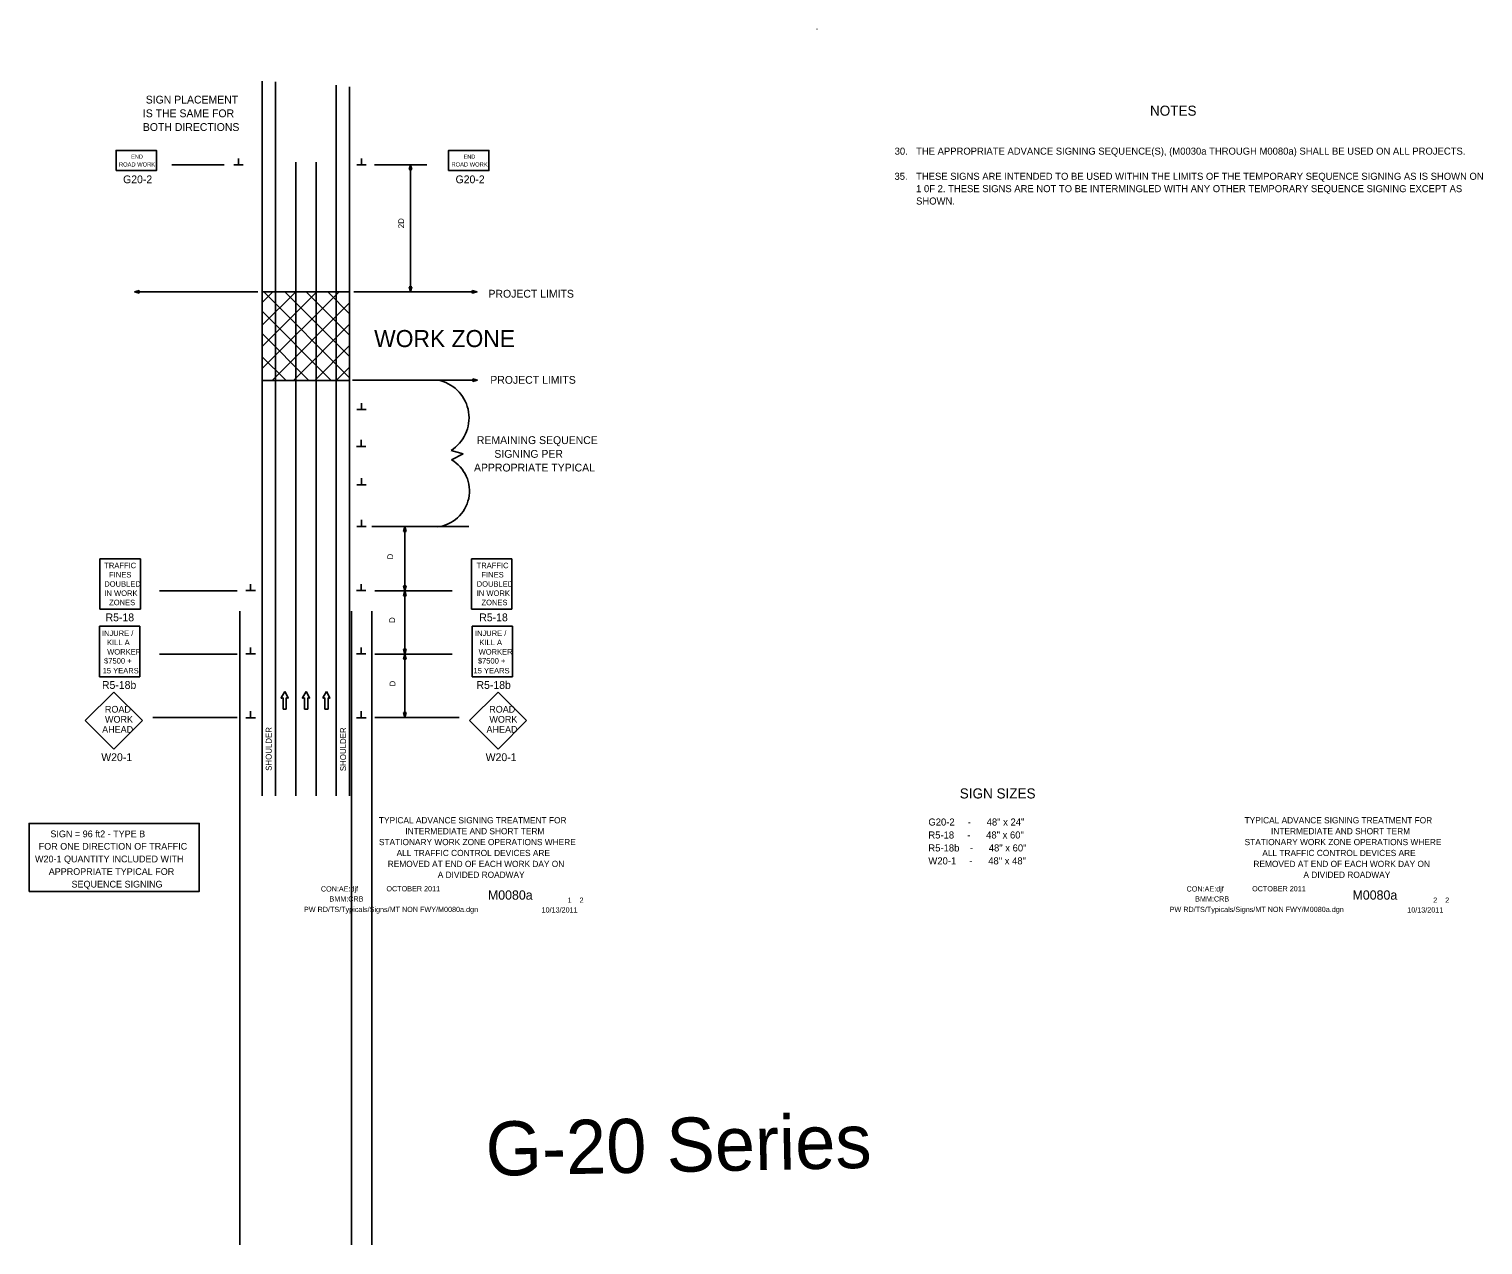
# Model space of a CAD drawing. Extents: x 16733 to 18461, y 5466 to 6911.
import ezdxf

# ---------------------------------------------------------------- set-up
doc = ezdxf.new("R2010")
doc.units = 0
for name, color, linetype in [('BORDER', 7, 'Continuous'), ('BORDER_SIGNAL_WO', 7, 'Continuous'), ('MT_SCRATCH_LEVEL_E', 7, 'Continuous'), ('PAVT_EDGE_EX', 7, 'Continuous'), ('TRAFFIC_SIGNS_PR', 7, 'Continuous'), ('TYPICAL_TEXT_DIMEN_PR', 7, 'Continuous')]:
    doc.layers.add(name, color=color, linetype=linetype)

msp = doc.modelspace()

# ---------------------------------------------------------------- linework, layer by layer
at = {"layer": 'BORDER'}
for p, q in [((17278.5, 5932.8), (17278.5, 5932.8)), ((18307.5, 5932.8), (18307.5, 5932.8)), ((18307.5, 5932.8), (18307.5, 5932.8))]:
    msp.add_line(p, q, dxfattribs=at)
at = {"layer": 'BORDER_SIGNAL_WO'}
msp.add_line((17670, 6911.2), (17669.5, 6911.3), dxfattribs=at)
at = {"layer": 'MT_SCRATCH_LEVEL_E'}
for p, q in [((17036.9, 6123.6), (17032.8, 6116.3)), ((17036.9, 6123.6), (17032.8, 6116.3)), ((17041, 6116.3), (17036.9, 6123.6)), ((17041, 6116.3), (17036.9, 6123.6)), ((17062.3, 6123.6), (17058.2, 6116.3)), ((17062.3, 6123.6), (17058.2, 6116.3)), ((17066.5, 6116.3), (17062.3, 6123.6)), ((17066.5, 6116.3), (17062.3, 6123.6)), ((17086.5, 6123.6), (17082.4, 6116.3)), ((17086.5, 6123.6), (17082.4, 6116.3)), ((17090.7, 6116.3), (17086.5, 6123.6)), ((17090.7, 6116.3), (17086.5, 6123.6)), ((17033.3, 6115.6), (17035, 6116)), ((17033.3, 6115.6), (17035, 6116)), ((17035, 6116), (17035, 6102.7)), ((17035, 6116), (17035, 6102.7)), ((17035, 6102.7), (17038.8, 6102.7)), ((17035, 6102.7), (17038.8, 6102.7)), ((17038.8, 6102.7), (17038.8, 6116)), ((17038.8, 6116), (17040.6, 6115.6)), ((17038.8, 6102.7), (17038.8, 6116)), ((17038.8, 6116), (17040.6, 6115.6)), ((17058.7, 6115.6), (17060.5, 6116)), ((17058.7, 6115.6), (17060.5, 6116)), ((17060.5, 6116), (17060.5, 6102.7)), ((17060.5, 6116), (17060.5, 6102.7)), ((17060.5, 6102.7), (17064.2, 6102.7)), ((17060.5, 6102.7), (17064.2, 6102.7)), ((17064.2, 6102.7), (17064.2, 6116)), ((17064.2, 6116), (17066, 6115.6)), ((17064.2, 6102.7), (17064.2, 6116)), ((17064.2, 6116), (17066, 6115.6)), ((17082.9, 6115.6), (17084.7, 6116)), ((17082.9, 6115.6), (17084.7, 6116)), ((17084.7, 6116), (17084.7, 6102.7)), ((17084.7, 6116), (17084.7, 6102.7)), ((17084.7, 6102.7), (17088.4, 6102.7)), ((17084.7, 6102.7), (17088.4, 6102.7)), ((17088.4, 6102.7), (17088.4, 6116)), ((17088.4, 6116), (17090.2, 6115.6)), ((17088.4, 6102.7), (17088.4, 6116)), ((17088.4, 6116), (17090.2, 6115.6))]:
    msp.add_line(p, q, dxfattribs=at)
for centre, start, end in [((17033.2, 6116.1), 150.4248, 279.9638), ((17033.2, 6116.1), 150.4248, 279.9638), ((17040.6, 6116.1), 260.0362, 29.7731), ((17040.6, 6116.1), 260.0362, 29.7731), ((17058.6, 6116.1), 150.4248, 279.9638), ((17058.6, 6116.1), 150.4248, 279.9638), ((17066.1, 6116.1), 260.0362, 29.7731), ((17066.1, 6116.1), 260.0362, 29.7731), ((17082.8, 6116.1), 150.4248, 279.9638), ((17082.8, 6116.1), 150.4248, 279.9638), ((17090.3, 6116.1), 260.0362, 29.7731), ((17090.3, 6116.1), 260.0362, 29.7731)]:
    msp.add_arc(centre, 0.463, start, end, dxfattribs=at)
at = {"layer": 'PAVT_EDGE_EX'}
for p, q in [((17010.1, 6849.3), (17010.1, 5999.6)), ((17026.1, 6848.5), (17026.1, 5999.6)), ((17098.1, 6844.8), (17098.1, 5999.6)), ((17114.1, 6842.6), (17114.1, 5999.6)), ((17050.1, 6753), (17050.1, 5999.6)), ((17074.1, 6753), (17074.1, 5999.6)), ((17009.9, 6507.2), (17101.6, 6598.8)), ((17010.1, 6586.1), (17022.8, 6598.8)), ((17114.1, 6598.8), (17010.2, 6598.8)), ((17010.3, 6534), (17074.8, 6598.6)), ((17010.3, 6559.1), (17049.8, 6598.6)), ((17114, 6496.6), (17011.9, 6598.8)), ((17021.5, 6493.2), (17114.1, 6585.9)), ((17114.1, 6522), (17037.1, 6599)), ((17114.1, 6547.5), (17062.5, 6599)), ((17114.1, 6572.9), (17088.4, 6598.7)), ((17098.1, 6599.3), (17098.1, 6493.5)), ((17114.1, 6598.4), (17113.7, 6598.8)), ((17114.1, 6493.5), (17114.1, 6598.8)), ((17092.2, 6493.6), (17010, 6575.8)), ((17047.3, 6493.6), (17114.1, 6560.4)), ((17065.7, 6493.5), (17010, 6549.3)), ((17072.6, 6493.5), (17114.1, 6534.9)), ((17038.2, 6493.7), (17009.8, 6522.1)), ((17098.1, 6493.5), (17114.1, 6509.5)), ((17010, 6493.5), (17114.1, 6493.5)), ((17098.1, 6493.5), (17114.1, 6493.5)), ((17098.1, 6493.5), (17098.1, 6493.5)), ((16983.7, 6219.1), (16983.7, 5465.7)), ((17116.3, 6219.1), (17116.3, 5465.7)), ((17140.3, 6219.1), (17140.3, 5465.7))]:
    msp.add_line(p, q, dxfattribs=at)
for points in [[(17050.1, 6753), (17050.1, 6728)], [(17050.1, 6753), (17050.1, 6728)], [(17074.1, 6753), (17074.1, 6728)], [(17050.1, 6653), (17050.1, 6628)], [(17074.1, 6653), (17074.1, 6628)], [(17050.1, 6453), (17050.1, 6428)], [(17074.1, 6453), (17074.1, 6428)], [(17050.1, 6353), (17050.1, 6328)], [(17074.1, 6353), (17074.1, 6328)], [(17050.1, 6253), (17050.1, 6228)], [(17074.1, 6253), (17074.1, 6228)], [(17050.1, 6153), (17050.1, 6128)], [(17074.1, 6153), (17074.1, 6128)], [(17050.1, 6053), (17050.1, 6028)], [(17074.1, 6053), (17074.1, 6028)]]:
    msp.add_lwpolyline(points, dxfattribs=at)
at = {"layer": 'TRAFFIC_SIGNS_PR'}
for p, q in [((16817.3, 6221.5), (16817.3, 6281.5)), ((16865.3, 6281.5), (16817.3, 6281.5)), ((16865.3, 6221.5), (16865.3, 6281.5)), ((17259, 6221.5), (17259, 6281.5)), ((17259, 6281.5), (17307, 6281.5)), ((17307, 6221.5), (17307, 6281.5)), ((16865.3, 6221.5), (16817.3, 6221.5)), ((17259, 6221.5), (17307, 6221.5)), ((16816.7, 6201.2), (16864.7, 6201.2)), ((16816.7, 6141.2), (16816.7, 6201.2)), ((16864.7, 6141.2), (16864.7, 6201.2)), ((17259.6, 6141.2), (17259.6, 6201.2)), ((17307.6, 6201.2), (17259.6, 6201.2)), ((17307.6, 6141.2), (17307.6, 6201.2)), ((16816.7, 6141.2), (16864.7, 6141.2)), ((17307.6, 6141.2), (17259.6, 6141.2)), ((16833.7, 6123.1), (16799.8, 6089.2)), ((16867.7, 6089.2), (16833.7, 6123.1)), ((17290.6, 6123.1), (17256.7, 6089.2)), ((17324.5, 6089.2), (17290.6, 6123.1)), ((16799.8, 6089.2), (16833.7, 6055.2)), ((16833.7, 6055.2), (16867.7, 6089.2)), ((17256.7, 6089.2), (17290.6, 6055.2)), ((17290.6, 6055.2), (17324.5, 6089.2))]:
    msp.add_line(p, q, dxfattribs=at)
at = {"layer": 'TYPICAL_TEXT_DIMEN_PR'}
for p, q in [((16982, 6749.8), (16982, 6757.6)), ((17128.1, 6749.8), (17128.1, 6757.6)), ((16902.6, 6749.9), (16964.9, 6749.9)), ((16982, 6749.8), (16976.4, 6749.8)), ((16987.6, 6749.8), (16982, 6749.8)), ((17128.1, 6749.8), (17122.5, 6749.8)), ((17133.7, 6749.8), (17128.1, 6749.8)), ((17143.5, 6750), (17205.9, 6750)), ((17185, 6744.2), (17186.6, 6750.1)), ((17186.6, 6744.2), (17185, 6744.2)), ((17186.5, 6749.9), (17186.5, 6599.1)), ((17186.6, 6750.1), (17188.1, 6744.2)), ((17188.1, 6744.2), (17186.6, 6744.2)), ((17186.6, 6598.9), (17185, 6604.8)), ((17185, 6604.8), (17186.6, 6604.8)), ((17186.6, 6604.8), (17188.1, 6604.8)), ((17188.1, 6604.8), (17186.6, 6598.9)), ((16864.1, 6600.4), (16858.2, 6598.8)), ((17005, 6598.8), (16858.2, 6598.8)), ((16858.2, 6598.8), (16864.1, 6597.2)), ((16864.1, 6598.8), (16864.1, 6600.4)), ((16864.1, 6597.2), (16864.1, 6598.8)), ((17119, 6598.8), (17265.8, 6598.8)), ((17259.9, 6598.8), (17259.9, 6600.4)), ((17259.9, 6600.4), (17265.8, 6598.8)), ((17265.8, 6598.8), (17259.9, 6597.2)), ((17259.9, 6597.2), (17259.9, 6598.8)), ((17117.5, 6493.9), (17266.2, 6493.9)), ((17260.4, 6493.9), (17260.4, 6495.4)), ((17260.4, 6495.4), (17266.2, 6493.9)), ((17266.2, 6493.9), (17260.4, 6492.3)), ((17260.4, 6492.3), (17260.4, 6493.9)), ((17128.2, 6458.9), (17128.2, 6466.7)), ((17128.2, 6458.9), (17122.6, 6458.9)), ((17133.8, 6458.9), (17128.2, 6458.9)), ((17127.9, 6415), (17122.3, 6415)), ((17127.9, 6415), (17127.9, 6422.8)), ((17133.5, 6415), (17127.9, 6415)), ((17234.6, 6410.2), (17249.2, 6406.4)), ((17249.2, 6406.4), (17235.2, 6399.3)), ((17128.2, 6369.4), (17128.2, 6377.2)), ((17128.2, 6369.4), (17122.6, 6369.4)), ((17133.8, 6369.4), (17128.2, 6369.4)), ((17128.2, 6319.9), (17128.2, 6327.7)), ((17128.2, 6319.9), (17122.6, 6319.9)), ((17133.8, 6319.9), (17128.2, 6319.9)), ((17140.6, 6319.9), (17255.8, 6319.9)), ((17178.2, 6314.1), (17179.8, 6319.9)), ((17179.8, 6314.1), (17178.2, 6314.1)), ((17179.8, 6319.9), (17179.8, 6168.1)), ((17179.8, 6319.9), (17181.4, 6314.1)), ((17181.4, 6314.1), (17179.8, 6314.1)), ((16980.3, 6243.5), (16888.2, 6243.5)), ((16990.8, 6243.7), (16996.4, 6243.7)), ((16996.4, 6243.7), (16996.4, 6251.5)), ((16996.4, 6243.7), (17002.1, 6243.7)), ((17127.9, 6243.7), (17122.3, 6243.7)), ((17127.9, 6243.7), (17127.9, 6251.5)), ((17133.5, 6243.7), (17127.9, 6243.7)), ((17144, 6243.5), (17236.1, 6243.5)), ((17179.8, 6243.5), (17178.2, 6249.4)), ((17178.2, 6249.4), (17179.8, 6249.4)), ((17178.2, 6237.6), (17179.8, 6243.5)), ((17179.8, 6249.4), (17181.4, 6249.4)), ((17181.4, 6249.4), (17179.8, 6243.5)), ((17179.8, 6243.5), (17181.4, 6237.6)), ((17179.8, 6237.6), (17178.2, 6237.6)), ((17181.4, 6237.6), (17179.8, 6237.6)), ((16996.4, 6168.3), (16996.4, 6176.1)), ((17127.9, 6168.3), (17127.9, 6176.1)), ((17179.8, 6168.1), (17178.2, 6174)), ((17178.2, 6174), (17179.8, 6174)), ((17179.8, 6174), (17181.4, 6174)), ((17181.4, 6174), (17179.8, 6168.1)), ((16980.3, 6168.1), (16888.2, 6168.1)), ((16990.8, 6168.3), (16996.4, 6168.3)), ((16996.4, 6168.3), (17002.1, 6168.3)), ((17127.9, 6168.3), (17122.3, 6168.3)), ((17133.5, 6168.3), (17127.9, 6168.3)), ((17144, 6168.1), (17236.1, 6168.1)), ((17178.2, 6162.2), (17179.8, 6168.1)), ((17179.8, 6162.2), (17178.2, 6162.2)), ((17179.8, 6168.1), (17179.8, 6092.7)), ((17179.8, 6168.1), (17181.4, 6162.2)), ((17181.4, 6162.2), (17179.8, 6162.2)), ((16996.4, 6092.5), (16996.4, 6100.3)), ((17127.9, 6092.5), (17127.9, 6100.3)), ((16980.3, 6092.7), (16880.1, 6092.7)), ((16990.8, 6092.5), (16996.4, 6092.5)), ((16996.4, 6092.5), (17002, 6092.5)), ((17127.9, 6092.5), (17122.3, 6092.5)), ((17133.6, 6092.5), (17127.9, 6092.5)), ((17144, 6092.7), (17244.2, 6092.7)), ((17179.8, 6092.7), (17178.2, 6098.6)), ((17178.2, 6098.6), (17179.8, 6098.6)), ((17179.8, 6098.6), (17181.4, 6098.6)), ((17181.4, 6098.6), (17179.8, 6092.7))]:
    msp.add_line(p, q, dxfattribs=at)
for points in [[(16836.5, 6743), (16884.5, 6743), (16884.5, 6767), (16836.5, 6767)], [(17231.7, 6743), (17279.7, 6743), (17279.7, 6767), (17231.7, 6767)], [(16733, 5885.9), (16935.4, 5885.9), (16935.4, 5966.8), (16733, 5966.8)]]:
    msp.add_lwpolyline(points, close=True, dxfattribs=at)
for centre, radius, start, end in [((17210.2, 6449), 45.8, 302.1563, 75.2517), ((17213.6, 6362.1), 42.9, 276.3375, 59.9789)]:
    msp.add_arc(centre, radius, start, end, dxfattribs=at)

# ---------------------------------------------------------------- texts
at = {"layer": 'BORDER_SIGNAL_WO'}
for s, height, p in [('TYPICAL ADVANCE SIGNING TREATMENT FOR', 7.391, (17148.9, 5966.9)), ('TYPICAL ADVANCE SIGNING TREATMENT FOR', 7.391, (18177.9, 5966.9)), ('STATIONARY WORK ZONE OPERATIONS WHERE', 7.391, (17148.9, 5941)), ('INTERMEDIATE AND SHORT TERM ', 7.391, (17180.3, 5953.9)), ('STATIONARY WORK ZONE OPERATIONS WHERE', 7.391, (18177.9, 5941)), ('INTERMEDIATE AND SHORT TERM ', 7.391, (18209.3, 5953.9)), ('ALL TRAFFIC CONTROL DEVICES ARE', 7.391, (17169.9, 5928)), ('ALL TRAFFIC CONTROL DEVICES ARE', 7.391, (18198.9, 5928)), ('REMOVED AT END OF EACH WORK DAY ON', 7.391, (17159.4, 5915)), ('REMOVED AT END OF EACH WORK DAY ON', 7.391, (18188.4, 5915)), ('A DIVIDED ROADWAY', 7.391, (17218.8, 5902.1)), ('A DIVIDED ROADWAY', 7.391, (18247.8, 5902.1)), ('CON:AE:djf', 6.2, (17079.9, 5885.9)), ('BMM:CRB   ', 6.2, (17090.1, 5874)), ('    OCTOBER 2011    ', 6.2, (17148.3, 5886.1)), ('    M0080a   ', 11, (17262.1, 5876.2)), (' 1    2 ', 6.2, (17370.7, 5872.5)), ('CON:AE:djf', 6.2, (18108.9, 5885.9)), ('BMM:CRB   ', 6.2, (18119.1, 5874)), ('    OCTOBER 2011    ', 6.2, (18177.3, 5886.1)), ('    M0080a   ', 11, (18289.8, 5876.2)), (' 2    2 ', 6.2, (18399.7, 5872.5)), ('PW RD/TS/Typicals/Signs/MT NON FWY/M0080a.dgn  ', 6.2, (17059.8, 5861.5)), ('10/13/2011    ', 6.2, (17342.2, 5860.9)), ('PW RD/TS/Typicals/Signs/MT NON FWY/M0080a.dgn  ', 6.2, (18088.8, 5861.5)), ('10/13/2011    ', 6.2, (18371.2, 5860.9))]:
    msp.add_text(s, height=height, dxfattribs=at).set_placement(p)
at = {"layer": 'TRAFFIC_SIGNS_PR'}
for s, height, p in [('SIGN PLACEMENT', 9.3, (16871.7, 6822.8)), ('IS THE SAME FOR', 9.3, (16868.3, 6806.5)), ('BOTH DIRECTIONS', 9.3, (16868.3, 6790.2)), ('G20-2', 9.3, (16844.8, 6728)), ('G20-2', 9.3, (17240, 6728)), ('PROJECT LIMITS', 9.3, (17279.1, 6592)), ('PROJECT LIMITS', 9.3, (17281.3, 6489.6)), ('REMAINING SEQUENCE', 9.3, (17265.3, 6417.9)), ('APPROPRIATE TYPICAL', 9.3, (17261.9, 6385.3)), ('SIGNING PER ', 9.3, (17286.1, 6401.6)), ('TRAFFIC', 6.5, (16822.4, 6270.3)), ('TRAFFIC', 6.5, (17265, 6270.3)), ('FINES', 6.5, (16828.2, 6259.3)), ('FINES', 6.5, (17270.8, 6259.3)), ('DOUBLED', 6.5, (16822.4, 6248.3)), ('IN WORK', 6.5, (16822.6, 6237.3)), ('DOUBLED', 6.5, (17265.1, 6248.3)), ('IN WORK', 6.5, (17265.2, 6237.3)), ('ZONES', 6.5, (16828.2, 6226.3)), ('ZONES', 6.5, (17270.8, 6226.3)), ('R5-18', 9.3, (16824, 6207.2)), ('R5-18', 9.3, (17268.2, 6207.2)), ('INJURE /', 6.5, (16819.6, 6189.7)), ('INJURE /', 6.5, (17263, 6189.7)), ('WORKER', 6.5, (16825.9, 6167.6)), ('KILL A', 6.5, (16825.7, 6178.8)), ('WORKER', 6.5, (17267.4, 6167.6)), ('KILL A', 6.5, (17268.3, 6178.8)), ('$7500 +', 6.5, (16822.2, 6156.9)), ('$7500 +', 6.5, (17266.5, 6156.9)), ('R5-18b', 9.3, (16819.7, 6126.8)), ('15 YEARS', 6.5, (16820.5, 6145.2)), ('15 YEARS', 6.5, (17261.3, 6145.2)), ('R5-18b', 9.3, (17264.9, 6126.8)), ('ROAD', 8, (16823.2, 6098.6)), ('ROAD', 8, (17280, 6098.6)), ('WORK', 8, (16823.3, 6086.6)), ('WORK', 8, (17280.2, 6086.6)), ('AHEAD', 8, (16819.9, 6074.6)), ('AHEAD', 8, (17276.8, 6074.6)), ('W20-1', 9.3, (16818.9, 6040.9)), ('W20-1', 9.3, (17275.8, 6040.9))]:
    msp.add_text(s, height=height, dxfattribs=at).set_placement(p)
at = {"layer": 'TYPICAL_TEXT_DIMEN_PR'}
for s, height, p in [('NOTES', 12, (18065.4, 6808.3)), ('END', 4.79, (16854.4, 6757.3)), ('END', 4.79, (17249.5, 6757.3)), ('30.', 8.4, (17761.9, 6762)), ('THE APPROPRIATE ADVANCE SIGNING SEQUENCE(S), (M0030a THROUGH M0080a) SHALL BE USED ON ALL PROJECTS.', 8.4, (17787.4, 6762)), ('ROAD WORK', 4.96, (16839.9, 6747.9)), ('ROAD WORK', 4.96, (17235.1, 6747.9)), ('35.', 8.4, (17761.7, 6732.1)), ('THESE SIGNS ARE INTENDED TO BE USED WITHIN THE LIMITS OF THE TEMPORARY SEQUENCE SIGNING AS IS SHOWN ON ', 8.4, (17787.4, 6732.1)), ('1 0F 2. THESE SIGNS ARE NOT TO BE INTERMINGLED WITH ANY OTHER TEMPORARY SEQUENCE SIGNING EXCEPT AS', 8.4, (17787.4, 6717.4)), ('SHOWN.', 8.4, (17787.4, 6702.7)), ('WORK ZONE', 20.31, (17143.2, 6533.2)), ('SIGN SIZES', 12, (17839.3, 5996.5)), ('G20-2     -      48" x 24"', 8.4, (17802, 5964.3)), ('SIGN = 96 ft2 - TYPE B', 8, (16758.4, 5950.4)), ('R5-18     -      48" x 60"', 8.4, (17802, 5948.9)), ('W20-1 QUANTITY INCLUDED WITH ', 8, (16740.1, 5920.6)), ('FOR ONE DIRECTION OF TRAFFIC', 8, (16744.5, 5935.6)), ('R5-18b    -      48" x 60"', 8.4, (17802, 5933.5)), ('APPROPRIATE TYPICAL FOR ', 8, (16756.4, 5905.6)), ('W20-1     -      48" x 48"', 8.4, (17802, 5918.1)), ('SEQUENCE SIGNING', 8, (16783.5, 5890.6))]:
    msp.add_text(s, height=height, dxfattribs=at).set_placement(p)
for s, height, rotation, p in [('2D', 7, 90, (17178.8, 6674.5)), ('D', 7, 90, (17165.8, 6280.7)), ('D', 7, 90, (17168.1, 6205.2)), ('D', 7, 90, (17168.5, 6129.7)), ('SHOULDER', 7, 90, (17021.4, 6029.4)), ('SHOULDER', 7, 90, (17109.8, 6029)), ('G-20 Series', 64.287, 1.2103, (17276.4, 5547.7))]:
    msp.add_text(s, height=height, rotation=rotation, dxfattribs=at).set_placement(p)

doc.saveas('drawing.dxf')
